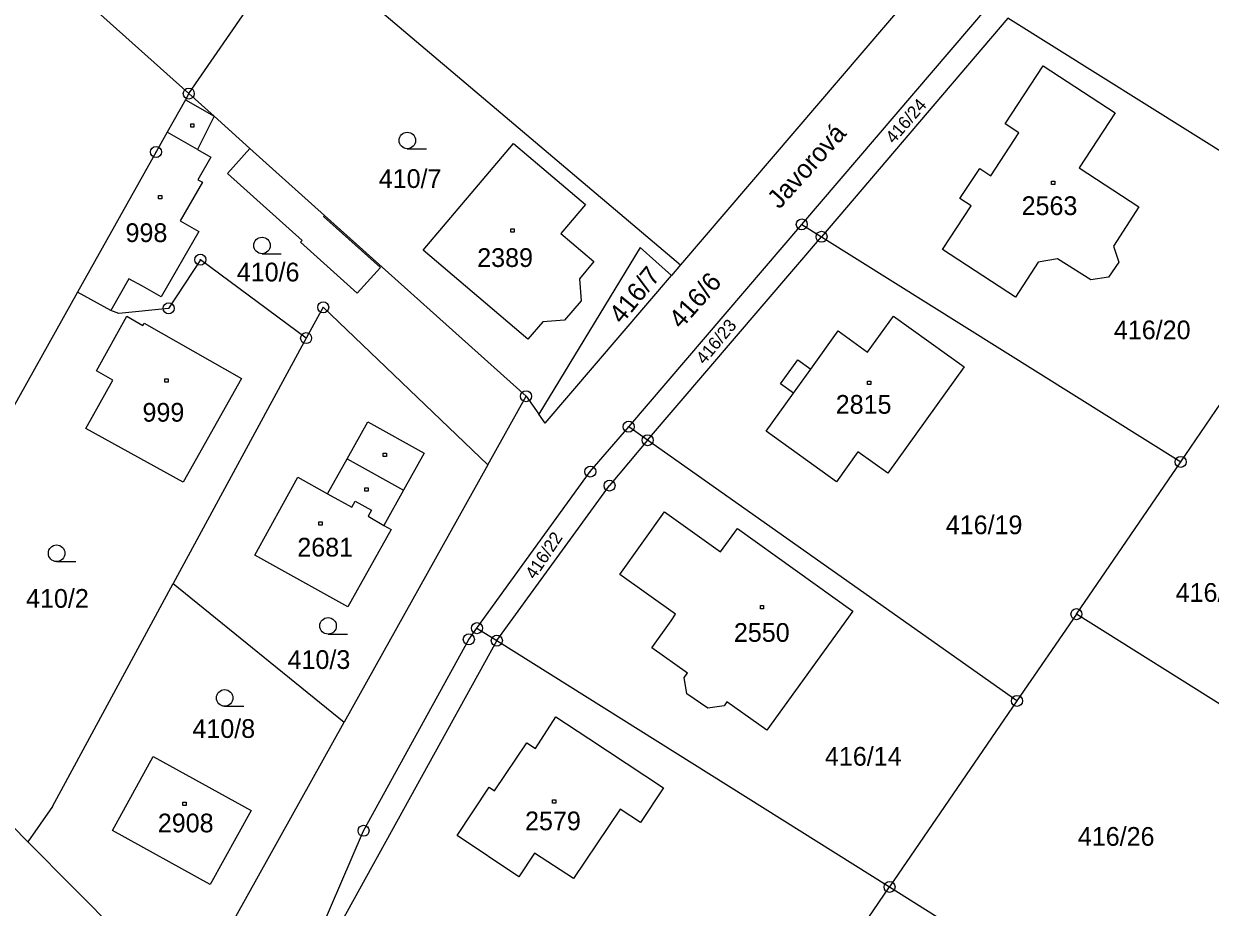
# Model space of a CAD drawing. Extents: x -795483 to -789093, y -1112258 to -1108741.
# Drawn here: x -791289.1 to -791181.5, y -1111080.2 to -1111000 of the extents above; entities that cross this region are included whole.
import ezdxf

# ---------------------------------------------------------------- set-up
doc = ezdxf.new("R2010")
doc.units = 0
for name, color, linetype in [('Vrstva 1', 7, 'Continuous'), ('Vrstva 14', 7, 'Continuous'), ('Vrstva 15', 7, 'Continuous'), ('Vrstva 2', 7, 'Continuous'), ('Vrstva 23', 7, 'Continuous'), ('Vrstva 25', 7, 'Continuous'), ('Vrstva 28', 7, 'Continuous'), ('Vrstva 38', 7, 'Continuous')]:
    doc.layers.add(name, color=color, linetype=linetype)

msp = doc.modelspace()

# ---------------------------------------------------------------- linework, layer by layer
at = {"layer": 'Vrstva 1'}
for p, q in [((-791274.15, -1111006.35), (-791264.45, -1110992.26)), ((-791287.82, -1110994.07), (-791274.15, -1111006.35)), ((-791262.82, -1110993.73), (-791229.56, -1111021.89)), ((-791207.97, -1110996.63), (-791229.56, -1111021.89)), ((-791218.55, -1111018.23), (-791201.6, -1110998.41)), ((-791199.85, -1110999.51), (-791216.76, -1111019.35)), ((-791170.66, -1111017.82), (-791199.85, -1110999.51)), ((-791200.1, -1111009.11), (-791196.66, -1111003.83)), ((-791196.66, -1111003.83), (-791190.12, -1111008.11)), ((-791274.15, -1111006.35), (-791274.46, -1111006.91)), ((-791271.86, -1111008.4), (-791274.15, -1111006.35)), ((-791274.46, -1111006.91), (-791276.11, -1111009.85)), ((-791271.86, -1111008.4), (-791273.36, -1111011.42)), ((-791268.6, -1111011.33), (-791271.86, -1111008.4)), ((-791190.12, -1111008.11), (-791193.39, -1111013.1)), ((-791198.86, -1111009.91), (-791200.1, -1111009.11)), ((-791276.11, -1111009.85), (-791277.12, -1111011.65)), ((-791201.41, -1111013.81), (-791198.86, -1111009.91)), ((-791277.12, -1111011.65), (-791284.26, -1111024.37)), ((-791273.36, -1111011.42), (-791272.15, -1111012.12)), ((-791261.83, -1111017.41), (-791268.6, -1111011.33)), ((-791252.88, -1111020.58), (-791244.7, -1111010.9)), ((-791244.7, -1111010.9), (-791238.16, -1111016.41)), ((-791272.15, -1111012.12), (-791273.32, -1111014.17)), ((-791204.2, -1111015.89), (-791202.41, -1111013.15)), ((-791202.41, -1111013.15), (-791201.41, -1111013.81)), ((-791193.39, -1111013.1), (-791187.99, -1111016.62)), ((-791272.91, -1111014.4), (-791274.93, -1111017.89)), ((-791273.32, -1111014.17), (-791272.91, -1111014.4)), ((-791203.2, -1111016.55), (-791204.2, -1111015.89)), ((-791238.16, -1111016.41), (-791240.4, -1111019.05)), ((-791205.78, -1111020.5), (-791203.2, -1111016.55)), ((-791187.99, -1111016.62), (-791190.27, -1111020.2)), ((-791274.93, -1111017.89), (-791273.24, -1111018.87)), ((-791243.56, -1111033.82), (-791261.83, -1111017.41)), ((-791234.25, -1111036.59), (-791218.55, -1111018.23)), ((-791218.55, -1111018.23), (-791216.76, -1111019.35)), ((-791273.24, -1111018.87), (-791276.66, -1111024.8)), ((-791240.4, -1111019.05), (-791237.4, -1111021.58)), ((-791232.53, -1111037.81), (-791216.76, -1111019.35)), ((-791216.76, -1111019.35), (-791184.18, -1111039.78)), ((-791233.21, -1111020.31), (-791242.41, -1111035.46)), ((-791230.38, -1111022.85), (-791233.21, -1111020.31)), ((-791199.17, -1111024.82), (-791205.78, -1111020.5)), ((-791190.27, -1111020.2), (-791189.79, -1111021.66)), ((-791273.1, -1111021.43), (-791275.98, -1111025.85)), ((-791263.51, -1111028.55), (-791273.1, -1111021.43)), ((-791243.39, -1111028.63), (-791252.88, -1111020.58)), ((-791237.4, -1111021.58), (-791238.72, -1111023.16)), ((-791195.37, -1111021.34), (-791197.1, -1111021.65)), ((-791192.32, -1111023.25), (-791195.37, -1111021.34)), ((-791229.56, -1111021.89), (-791230.38, -1111022.85)), ((-791197.1, -1111021.65), (-791199.17, -1111024.82)), ((-791189.79, -1111021.66), (-791190.72, -1111023.03)), ((-791279.6, -1111023.18), (-791281.22, -1111026.05)), ((-791278.35, -1111023.82), (-791279.6, -1111023.18)), ((-791241.84, -1111036.26), (-791230.38, -1111022.85)), ((-791238.72, -1111023.16), (-791238.55, -1111025.15)), ((-791190.72, -1111023.03), (-791192.32, -1111023.25)), ((-791284.26, -1111024.37), (-791303.7, -1111059.05)), ((-791281.22, -1111026.05), (-791284.26, -1111024.37)), ((-791276.66, -1111024.8), (-791278.35, -1111023.82)), ((-791275.98, -1111025.85), (-791280.49, -1111026.31)), ((-791261.96, -1111025.75), (-791263.51, -1111028.55)), ((-791247.04, -1111040.06), (-791261.96, -1111025.75)), ((-791238.55, -1111025.15), (-791240.06, -1111026.93)), ((-791282.51, -1111031.51), (-791279.76, -1111026.55)), ((-791280.49, -1111026.31), (-791281.22, -1111026.05)), ((-791279.76, -1111026.55), (-791278.31, -1111027.4)), ((-791240.06, -1111026.93), (-791242.05, -1111027.07)), ((-791212.58, -1111029.82), (-791210.22, -1111026.56)), ((-791210.22, -1111026.56), (-791203.81, -1111031.15)), ((-791278.31, -1111027.4), (-791278.19, -1111027.18)), ((-791278.19, -1111027.18), (-791269.38, -1111032.2)), ((-791242.05, -1111027.07), (-791243.39, -1111028.63)), ((-791217.74, -1111031.36), (-791215.26, -1111027.88)), ((-791215.26, -1111027.88), (-791212.58, -1111029.82)), ((-791263.51, -1111028.55), (-791275.57, -1111050.83)), ((-791220.47, -1111032.69), (-791218.91, -1111030.51)), ((-791218.91, -1111030.51), (-791217.74, -1111031.36)), ((-791203.81, -1111031.15), (-791210.76, -1111040.81)), ((-791283.48, -1111036.76), (-791281.05, -1111032.36)), ((-791281.05, -1111032.36), (-791282.51, -1111031.51)), ((-791269.38, -1111032.2), (-791274.66, -1111041.63)), ((-791219.31, -1111033.53), (-791220.47, -1111032.69)), ((-791247.04, -1111040.06), (-791243.56, -1111033.82)), ((-791243.56, -1111033.82), (-791242.41, -1111035.46)), ((-791221.79, -1111036.99), (-791219.31, -1111033.53)), ((-791241.84, -1111036.26), (-791242.41, -1111035.46)), ((-791259.79, -1111039.49), (-791257.92, -1111036.13)), ((-791257.92, -1111036.13), (-791252.81, -1111039)), ((-791237.73, -1111040.66), (-791234.25, -1111036.59)), ((-791232.53, -1111037.81), (-791234.25, -1111036.59)), ((-791274.66, -1111041.63), (-791283.48, -1111036.76)), ((-791215.41, -1111041.58), (-791221.79, -1111036.99)), ((-791232.53, -1111037.81), (-791235.99, -1111041.93)), ((-791199.03, -1111061.47), (-791232.53, -1111037.81)), ((-791261.57, -1111042.67), (-791259.79, -1111039.49)), ((-791252.81, -1111039), (-791254.69, -1111042.36)), ((-791213.46, -1111038.87), (-791215.41, -1111041.58)), ((-791210.76, -1111040.81), (-791213.46, -1111038.87)), ((-791193.64, -1111053.6), (-791184.18, -1111039.78)), ((-791247.04, -1111040.06), (-791260.07, -1111063.41)), ((-791248.01, -1111054.87), (-791237.73, -1111040.66)), ((-791268.16, -1111048.23), (-791264.25, -1111041.18)), ((-791264.25, -1111041.18), (-791261.57, -1111042.67)), ((-791246.21, -1111056), (-791235.99, -1111041.93)), ((-791254.69, -1111042.36), (-791256.45, -1111045.54)), ((-791235.06, -1111050), (-791231.01, -1111044.3)), ((-791231.01, -1111044.3), (-791225.93, -1111047.93)), ((-791255.81, -1111045.91), (-791259.73, -1111052.94)), ((-791256.45, -1111045.54), (-791255.81, -1111045.91)), ((-791225.93, -1111047.93), (-791224.39, -1111045.82)), ((-791224.39, -1111045.82), (-791213.92, -1111053.33)), ((-791259.73, -1111052.94), (-791268.16, -1111048.23)), ((-791230.01, -1111053.59), (-791235.06, -1111050)), ((-791286.5, -1111071.04), (-791275.57, -1111050.83)), ((-791275.57, -1111050.83), (-791260.07, -1111063.41)), ((-791230.4, -1111054.19), (-791230.01, -1111053.59)), ((-791213.92, -1111053.33), (-791221.71, -1111064.14)), ((-791193.64, -1111053.6), (-791199.03, -1111061.47)), ((-791168.22, -1111069.56), (-791193.64, -1111053.6)), ((-791248.75, -1111055.89), (-791248.01, -1111054.87)), ((-791248.01, -1111054.87), (-791246.21, -1111056)), ((-791232.16, -1111056.66), (-791230.4, -1111054.19)), ((-791246.21, -1111056), (-791265.46, -1111090.81)), ((-791258.3, -1111073.26), (-791248.75, -1111055.89)), ((-791246.21, -1111056), (-791210.59, -1111078.35)), ((-791228.93, -1111058.96), (-791232.16, -1111056.66)), ((-791303.7, -1111059.05), (-791288.76, -1111074.26)), ((-791229.23, -1111059.36), (-791228.93, -1111058.96)), ((-791228.97, -1111060.84), (-791229.23, -1111059.36)), ((-791227.06, -1111062.13), (-791228.97, -1111060.84)), ((-791225.6, -1111061.91), (-791227.06, -1111062.13)), ((-791225.34, -1111061.56), (-791225.6, -1111061.91)), ((-791221.71, -1111064.14), (-791225.34, -1111061.56)), ((-791199.03, -1111061.47), (-791210.59, -1111078.35)), ((-791274.25, -1111088.84), (-791260.07, -1111063.41)), ((-791242.7, -1111065.8), (-791240.85, -1111062.91)), ((-791240.85, -1111062.91), (-791237.86, -1111064.87)), ((-791246.42, -1111069.64), (-791243.49, -1111065.29)), ((-791243.49, -1111065.29), (-791242.7, -1111065.8)), ((-791237.86, -1111064.87), (-791231.08, -1111069.36)), ((-791281.08, -1111073.23), (-791277.37, -1111066.52)), ((-791277.37, -1111066.52), (-791268.5, -1111071.43)), ((-791249.82, -1111073.7), (-791246.91, -1111069.31)), ((-791246.91, -1111069.31), (-791246.42, -1111069.64)), ((-791231.08, -1111069.36), (-791233.17, -1111072.51)), ((-791286.5, -1111071.04), (-791288.76, -1111074.26)), ((-791268.5, -1111071.43), (-791272.21, -1111078.14)), ((-791235.03, -1111071.3), (-791239.26, -1111077.6)), ((-791233.17, -1111072.51), (-791235.03, -1111071.3)), ((-791272.21, -1111078.14), (-791281.08, -1111073.23)), ((-791266.42, -1111092.04), (-791258.3, -1111073.26)), ((-791288.76, -1111074.26), (-791274.25, -1111088.84)), ((-791244.21, -1111077.45), (-791249.82, -1111073.7)), ((-791242.78, -1111075.3), (-791244.21, -1111077.45)), ((-791239.26, -1111077.6), (-791242.78, -1111075.3)), ((-791233.75, -1111112.17), (-791210.59, -1111078.35)), ((-791210.59, -1111078.35), (-791185.22, -1111094.26))]:
    msp.add_line(p, q, dxfattribs=at)
msp.add_lwpolyline([(-791184.18, -1111039.78), (-791178.72, -1111031.8), (-791173.52, -1111022.78)], dxfattribs=at)
at = {"layer": 'Vrstva 2'}
for p, q in [((-791274.46, -1111006.91), (-791271.86, -1111008.4)), ((-791273.36, -1111011.42), (-791276.11, -1111009.85)), ((-791268.6, -1111011.33), (-791270.64, -1111013.6)), ((-791270.64, -1111013.6), (-791263.87, -1111019.69)), ((-791261.83, -1111017.41), (-791261.92, -1111017.51)), ((-791256.77, -1111022.13), (-791261.92, -1111017.51)), ((-791263.87, -1111019.69), (-791264.02, -1111019.85)), ((-791264.02, -1111019.85), (-791258.87, -1111024.47)), ((-791258.87, -1111024.47), (-791256.77, -1111022.13)), ((-791219.31, -1111033.53), (-791217.74, -1111031.36)), ((-791259.79, -1111039.49), (-791254.69, -1111042.36)), ((-791261.57, -1111042.67), (-791259.37, -1111043.89)), ((-791259.37, -1111043.89), (-791259.06, -1111043.34)), ((-791259.06, -1111043.34), (-791257.58, -1111044.16)), ((-791257.58, -1111044.16), (-791257.87, -1111044.71)), ((-791257.87, -1111044.71), (-791256.45, -1111045.54))]:
    msp.add_line(p, q, dxfattribs=at)
at = {"layer": 'Vrstva 23'}
for p, q in [((-791254.33, -1111011.36), (-791252.58, -1111011.36)), ((-791267.51, -1111020.89), (-791265.76, -1111020.89)), ((-791286.14, -1111048.82), (-791284.39, -1111048.82)), ((-791261.52, -1111055.41), (-791259.77, -1111055.41)), ((-791270.9, -1111061.95), (-791269.15, -1111061.95))]:
    msp.add_line(p, q, dxfattribs=at)
for centre in [(-791254.33, -1111010.61), (-791267.51, -1111020.14), (-791286.14, -1111048.07), (-791261.52, -1111054.66), (-791270.9, -1111061.2)]:
    msp.add_circle(centre, 0.75, dxfattribs=at)
at = {"layer": 'Vrstva 25'}
for p, q in [((-791273.98, -1111009.11), (-791273.68, -1111009.11)), ((-791273.98, -1111009.41), (-791273.98, -1111009.11)), ((-791273.68, -1111009.41), (-791273.98, -1111009.41)), ((-791273.68, -1111009.11), (-791273.68, -1111009.41)), ((-791195.89, -1111014.3), (-791195.59, -1111014.3)), ((-791195.89, -1111014.6), (-791195.89, -1111014.3)), ((-791195.59, -1111014.6), (-791195.89, -1111014.6)), ((-791195.59, -1111014.3), (-791195.59, -1111014.6)), ((-791276.91, -1111015.6), (-791276.61, -1111015.6)), ((-791276.91, -1111015.9), (-791276.91, -1111015.6)), ((-791276.61, -1111015.9), (-791276.91, -1111015.9)), ((-791276.61, -1111015.6), (-791276.61, -1111015.9)), ((-791244.94, -1111018.62), (-791244.64, -1111018.62)), ((-791244.94, -1111018.92), (-791244.94, -1111018.62)), ((-791244.64, -1111018.92), (-791244.94, -1111018.92)), ((-791244.64, -1111018.62), (-791244.64, -1111018.92)), ((-791276.32, -1111032.23), (-791276.02, -1111032.23)), ((-791276.32, -1111032.53), (-791276.32, -1111032.23)), ((-791276.02, -1111032.23), (-791276.02, -1111032.53)), ((-791276.02, -1111032.53), (-791276.32, -1111032.53)), ((-791212.59, -1111032.45), (-791212.29, -1111032.45)), ((-791212.59, -1111032.75), (-791212.59, -1111032.45)), ((-791212.29, -1111032.75), (-791212.59, -1111032.75)), ((-791212.29, -1111032.45), (-791212.29, -1111032.75)), ((-791256.52, -1111039), (-791256.22, -1111039)), ((-791256.52, -1111039.3), (-791256.52, -1111039)), ((-791256.22, -1111039.3), (-791256.52, -1111039.3)), ((-791256.22, -1111039), (-791256.22, -1111039.3)), ((-791258.19, -1111042.13), (-791257.89, -1111042.13)), ((-791258.19, -1111042.43), (-791258.19, -1111042.13)), ((-791257.89, -1111042.43), (-791258.19, -1111042.43)), ((-791257.89, -1111042.13), (-791257.89, -1111042.43)), ((-791262.35, -1111045.22), (-791262.05, -1111045.22)), ((-791262.35, -1111045.52), (-791262.35, -1111045.22)), ((-791262.05, -1111045.22), (-791262.05, -1111045.52)), ((-791262.05, -1111045.52), (-791262.35, -1111045.52)), ((-791222.31, -1111052.81), (-791222.01, -1111052.81)), ((-791222.31, -1111053.11), (-791222.31, -1111052.81)), ((-791222.01, -1111052.81), (-791222.01, -1111053.11)), ((-791222.01, -1111053.11), (-791222.31, -1111053.11)), ((-791274.68, -1111070.67), (-791274.38, -1111070.67)), ((-791274.68, -1111070.97), (-791274.68, -1111070.67)), ((-791274.38, -1111070.97), (-791274.68, -1111070.97)), ((-791274.38, -1111070.67), (-791274.38, -1111070.97)), ((-791241.17, -1111070.45), (-791240.87, -1111070.45)), ((-791241.17, -1111070.75), (-791241.17, -1111070.45)), ((-791240.87, -1111070.75), (-791241.17, -1111070.75)), ((-791240.87, -1111070.45), (-791240.87, -1111070.75))]:
    msp.add_line(p, q, dxfattribs=at)
at = {"layer": 'Vrstva 28'}
for centre, radius in [((-791274.15, -1111006.35), 0.5), ((-791274.15, -1111006.35), 0.01), ((-791277.12, -1111011.65), 0.5), ((-791277.12, -1111011.65), 0.01), ((-791218.55, -1111018.23), 0.5), ((-791218.55, -1111018.23), 0.01), ((-791216.76, -1111019.35), 0.5), ((-791216.76, -1111019.35), 0.01), ((-791273.1, -1111021.43), 0.5), ((-791273.1, -1111021.43), 0.01), ((-791275.98, -1111025.85), 0.5), ((-791275.98, -1111025.85), 0.01), ((-791261.96, -1111025.75), 0.5), ((-791261.96, -1111025.75), 0.01), ((-791263.51, -1111028.55), 0.5), ((-791263.51, -1111028.55), 0.01), ((-791243.56, -1111033.82), 0.5), ((-791243.56, -1111033.82), 0.01), ((-791234.25, -1111036.59), 0.5), ((-791234.25, -1111036.59), 0.01), ((-791232.53, -1111037.81), 0.5), ((-791232.53, -1111037.81), 0.01), ((-791184.18, -1111039.78), 0.5), ((-791184.18, -1111039.78), 0.01), ((-791237.73, -1111040.66), 0.5), ((-791237.73, -1111040.66), 0.01), ((-791235.99, -1111041.93), 0.5), ((-791235.99, -1111041.93), 0.01), ((-791193.64, -1111053.6), 0.5), ((-791193.64, -1111053.6), 0.01), ((-791248.01, -1111054.87), 0.5), ((-791248.01, -1111054.87), 0.01), ((-791248.75, -1111055.89), 0.5), ((-791248.75, -1111055.89), 0.01), ((-791246.21, -1111056), 0.5), ((-791246.21, -1111056), 0.01), ((-791199.03, -1111061.47), 0.5), ((-791199.03, -1111061.47), 0.01), ((-791258.3, -1111073.26), 0.5), ((-791258.3, -1111073.26), 0.01), ((-791210.59, -1111078.35), 0.5), ((-791210.59, -1111078.35), 0.01)]:
    msp.add_circle(centre, radius, dxfattribs=at)

# ---------------------------------------------------------------- texts
at = {"layer": 'Vrstva 14'}
for s, height, rotation, p in [('416/24', 1.14, 49.1223, (-791210.2, -1111010.97)), ('416/7', 1.7, 50.9571, (-791234.86, -1111027.36)), ('416/6', 1.7, 48.6307, (-791229.49, -1111027.8)), ('416/23', 1.14, 50.1774, (-791227.38, -1111031.01)), ('416/22', 1.14, 56.3099, (-791242.77, -1111050.51))]:
    msp.add_text(s, height=height, rotation=rotation, dxfattribs=at).set_placement(p)
for s, p in [('410/7', (-791256.92, -1111014.92)), ('410/6', (-791269.8, -1111023.4)), ('416/20', (-791190.24, -1111028.65)), ('416/19', (-791205.49, -1111046.34)), ('416/29', (-791184.64, -1111052.48)), ('410/2', (-791288.91, -1111053.02)), ('410/3', (-791265.19, -1111058.57)), ('410/8', (-791273.82, -1111064.83)), ('416/14', (-791216.45, -1111067.35)), ('416/26', (-791193.51, -1111074.62))]:
    msp.add_text(s, height=1.7, dxfattribs=at).set_placement(p)
at = {"layer": 'Vrstva 15'}
for s, p in [('2563', (-791198.61, -1111017.38)), ('998', (-791279.89, -1111019.83)), ('2389', (-791247.99, -1111022.09)), ('999', (-791278.35, -1111036.13)), ('2815', (-791215.47, -1111035.41)), ('2681', (-791264.31, -1111048.37)), ('2550', (-791224.71, -1111056.11)), ('2908', (-791276.96, -1111073.4)), ('2579', (-791243.65, -1111073.21))]:
    msp.add_text(s, height=1.7, dxfattribs=at).set_placement(p)
at = {"layer": 'Vrstva 38'}
msp.add_text('Javorová', height=1.7, rotation=48.0606, dxfattribs=at).set_placement((-791220.58, -1111016.91))

doc.saveas('drawing.dxf')
